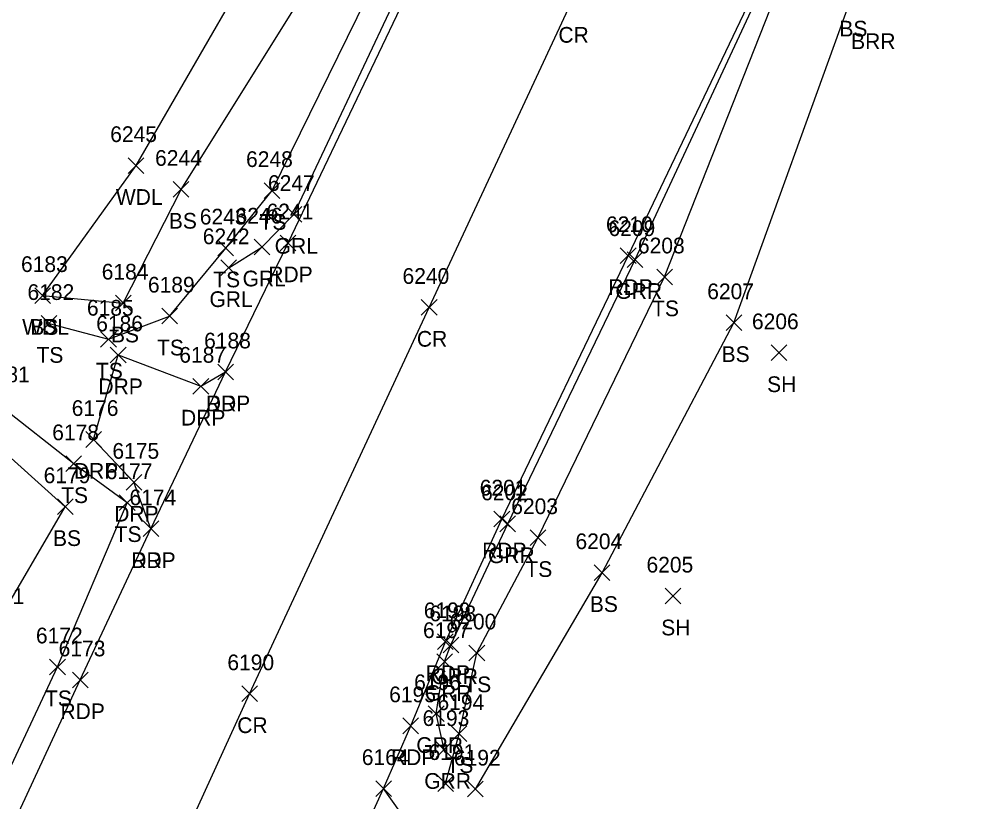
# Model space of a CAD drawing. Extents: x 1611797 to 1633212, y 298978 to 305475.
# Drawn here: x 1623086.6 to 1623208, y 302519.8 to 302619.4 of the extents above; entities that cross this region are included whole.
import ezdxf

# ---------------------------------------------------------------- set-up
doc = ezdxf.new("R2010")
doc.units = 0
for name, color, linetype in [('L_A', 7, 'Continuous'), ('L_I', 7, 'Continuous'), ('L_TIC', 7, 'Continuous'), ('LAWA', 7, 'Continuous'), ('LELB', 7, 'Continuous'), ('P_A', 7, 'Continuous'), ('P_I', 7, 'Continuous'), ('P_TIC', 7, 'Continuous'), ('PET', 7, 'Continuous'), ('PRC', 7, 'Continuous'), ('R_A', 7, 'Continuous'), ('R_I', 7, 'Continuous'), ('R_TIC', 7, 'Continuous'), ('RDP', 7, 'Continuous'), ('RGR', 7, 'Continuous')]:
    doc.layers.add(name, color=color, linetype=linetype)

msp = doc.modelspace()

# ---------------------------------------------------------------- linework, layer by layer
at = {"layer": 'L_TIC'}
for points in [[(1623100.54, 302599.79), (1623102.54, 302601.79)], [(1623102.54, 302599.79), (1623100.54, 302601.79)], [(1623106.26, 302596.76), (1623108.26, 302598.76)], [(1623108.26, 302596.76), (1623106.26, 302598.76)], [(1623117.84, 302596.61), (1623119.84, 302598.61)], [(1623119.84, 302596.61), (1623117.84, 302598.61)], [(1623111.95, 302589.29), (1623113.95, 302591.29)], [(1623113.95, 302589.29), (1623111.95, 302591.29)], [(1623167.79, 302585.61), (1623169.79, 302587.61)], [(1623169.79, 302585.61), (1623167.79, 302587.61)], [(1623088.63, 302583.24), (1623090.63, 302585.24)], [(1623090.63, 302583.24), (1623088.63, 302585.24)], [(1623088.63, 302583.24), (1623090.63, 302585.24)], [(1623090.63, 302583.24), (1623088.63, 302585.24)], [(1623098.9, 302582.28), (1623100.9, 302584.28)], [(1623100.9, 302582.28), (1623098.9, 302584.28)], [(1623104.79, 302580.62), (1623106.79, 302582.62)], [(1623106.79, 302580.62), (1623104.79, 302582.62)], [(1623089.45, 302579.68), (1623091.45, 302581.68)], [(1623091.45, 302579.68), (1623089.45, 302581.68)], [(1623176.61, 302579.78), (1623178.61, 302581.78)], [(1623178.61, 302579.78), (1623176.61, 302581.78)], [(1623097.02, 302577.68), (1623099.02, 302579.68)], [(1623099.02, 302577.68), (1623097.02, 302579.68)], [(1623182.35, 302575.95), (1623184.35, 302577.95)], [(1623184.35, 302575.95), (1623182.35, 302577.95)], [(1623092.6, 302561.82), (1623094.6, 302563.82)], [(1623094.6, 302561.82), (1623092.6, 302563.82)], [(1623091.52, 302556.35), (1623093.52, 302558.35)], [(1623093.52, 302556.35), (1623091.52, 302558.35)], [(1623099.4, 302556.86), (1623101.4, 302558.86)], [(1623101.4, 302556.86), (1623099.4, 302558.86)], [(1623151.67, 302552.41), (1623153.67, 302554.41)], [(1623153.67, 302552.41), (1623151.67, 302554.41)], [(1623159.84, 302547.95), (1623161.84, 302549.95)], [(1623161.84, 302547.95), (1623159.84, 302549.95)], [(1623168.87, 302544.97), (1623170.87, 302546.97)], [(1623170.87, 302544.97), (1623168.87, 302546.97)], [(1623143.9, 302537.73), (1623145.9, 302539.73)], [(1623145.9, 302537.73), (1623143.9, 302539.73)], [(1623090.53, 302535.95), (1623092.53, 302537.95)], [(1623092.53, 302535.95), (1623090.53, 302537.95)], [(1623141.63, 302527.45), (1623143.63, 302529.45)], [(1623143.63, 302527.45), (1623141.63, 302529.45)], [(1623139.92, 302521.1), (1623141.92, 302523.1)], [(1623141.92, 302521.1), (1623139.92, 302523.1)], [(1623143.72, 302520.39), (1623145.72, 302522.39)], [(1623145.72, 302520.39), (1623143.72, 302522.39)]]:
    msp.add_lwpolyline(points, dxfattribs=at)
at = {"layer": 'LAWA'}
msp.add_lwpolyline([(1623089.63, 302584.24), (1623101.54, 302600.79), (1623122.61, 302637.35), (1623140.17, 302675.92), (1623163.99, 302713.64)], dxfattribs=at)
at = {"layer": 'LELB'}
for points in [[(1623089.63, 302584.24), (1623099.9, 302583.28), (1623107.26, 302597.76), (1623129.85, 302633.91), (1623148.41, 302673.51), (1623161.31, 302708.12)], [(1623090.45, 302580.68), (1623098.02, 302578.68), (1623105.79, 302581.62), (1623112.95, 302590.29), (1623118.84, 302597.61), (1623135.63, 302631.86), (1623154.31, 302669.97), (1623172.76, 302707.09)], [(1623144.72, 302521.39), (1623160.84, 302548.95), (1623177.61, 302580.78), (1623192.6, 302622.23), (1623197.81, 302638.32), (1623201.61, 302657.13), (1623198.11, 302649.64), (1623197.81, 302649.3), (1623196.29, 302649.84)], [(1623140.92, 302522.1), (1623142.63, 302528.45), (1623144.9, 302538.73), (1623152.67, 302553.41), (1623168.79, 302586.61), (1623184.25, 302625.88), (1623194.89, 302644.22), (1623196.29, 302649.84), (1623195.84, 302653.9)], [(1622950.2, 302222.12), (1622969.04, 302263.04), (1622991.81, 302315.75), (1623013.56, 302366.12), (1623032.7, 302408.93), (1623054.15, 302459.64), (1623073.2, 302497.88), (1623091.53, 302536.95), (1623100.4, 302557.86), (1623093.6, 302562.82), (1623084.23, 302570.2)], [(1622931.41, 302188.46), (1622945.9, 302223.87), (1622965.15, 302265.23), (1622981.73, 302318.97), (1623007.17, 302368.65), (1623023.76, 302413.43), (1623043.88, 302464.02), (1623063.71, 302502.31), (1623083.53, 302541.97), (1623092.52, 302557.35), (1623082.99, 302565.85)]]:
    msp.add_lwpolyline(points, dxfattribs=at)
at = {"layer": 'P_TIC'}
for points in [[(1623119.88, 302589.94), (1623121.88, 302591.94)], [(1623121.88, 302589.94), (1623119.88, 302591.94)], [(1623163.16, 302588.32), (1623165.16, 302590.32)], [(1623165.16, 302588.32), (1623163.16, 302590.32)], [(1623137.83, 302581.73), (1623139.83, 302583.73)], [(1623139.83, 302581.73), (1623137.83, 302583.73)], [(1623111.93, 302573.51), (1623113.93, 302575.51)], [(1623113.93, 302573.51), (1623111.93, 302575.51)], [(1623147.08, 302554.78), (1623149.08, 302556.78)], [(1623149.08, 302554.78), (1623147.08, 302556.78)], [(1623102.43, 302553.54), (1623104.43, 302555.54)], [(1623104.43, 302553.54), (1623102.43, 302555.54)], [(1623139.9, 302539.16), (1623141.9, 302541.16)], [(1623141.9, 302539.16), (1623139.9, 302541.16)], [(1623093.42, 302534.3), (1623095.42, 302536.3)], [(1623095.42, 302534.3), (1623093.42, 302536.3)], [(1623114.97, 302532.53), (1623116.97, 302534.53)], [(1623116.97, 302532.53), (1623114.97, 302534.53)], [(1623135.48, 302528.45), (1623137.48, 302530.45)], [(1623137.48, 302528.45), (1623135.48, 302530.45)], [(1623132.04, 302520.46), (1623134.04, 302522.46)], [(1623134.04, 302520.46), (1623132.04, 302522.46)]]:
    msp.add_lwpolyline(points, dxfattribs=at)
at = {"layer": 'PET'}
for points in [[(1623120.03, 302492.78), (1623133.04, 302521.46), (1623136.48, 302529.45), (1623140.9, 302540.16), (1623148.08, 302555.78), (1623164.16, 302589.32), (1623182.09, 302626.91), (1623191.33, 302646.49), (1623194.97, 302654.45), (1623201.31, 302667.61), (1623213.02, 302692.54), (1623225.2, 302718.17), (1623242.57, 302754.17), (1623259.21, 302788.55), (1623275.23, 302819.9), (1623295.03, 302859.4), (1623316.4, 302901.79), (1623339.64, 302948.93), (1623359.43, 302990.05)], [(1623076.29, 302496.29), (1623094.42, 302535.3), (1623103.43, 302554.54), (1623112.93, 302574.51), (1623120.88, 302590.94), (1623139.35, 302629.62), (1623157.41, 302668.38), (1623174.94, 302705.43), (1623186.21, 302730.25), (1623197.28, 302753.3), (1623215.25, 302789.44), (1623239.94, 302839.72), (1623260.09, 302881.17), (1623281.2, 302923.51), (1623300.84, 302962.45)]]:
    msp.add_lwpolyline(points, dxfattribs=at)
at = {"layer": 'PRC'}
msp.add_lwpolyline([(1623094.71, 302486.97), (1623115.97, 302533.53), (1623138.83, 302582.73), (1623156.84, 302621.44), (1623174.33, 302658.65), (1623188.23, 302687.86), (1623204.65, 302721.63), (1623215.97, 302745.6), (1623233.17, 302781.9), (1623256.83, 302830.92), (1623277.73, 302872.44), (1623298.56, 302913.98), (1623318.04, 302953.14), (1623338.32, 302993.92), (1623366.3, 303050.96), (1623402.18, 303124.24), (1623426.64, 303170.43), (1623450.1, 303214.26), (1623478.76, 303269.12), (1623500.2, 303310.64), (1623518.37, 303345.45)], dxfattribs=at)
at = {"layer": 'R_TIC'}
for points in [[(1623120.62, 302593.57), (1623122.62, 302595.57)], [(1623122.62, 302593.57), (1623120.62, 302595.57)], [(1623116.55, 302589.41), (1623118.55, 302591.41)], [(1623118.55, 302589.41), (1623116.55, 302591.41)], [(1623164.04, 302587.82), (1623166.04, 302589.82)], [(1623166.04, 302587.82), (1623164.04, 302589.82)], [(1623112.32, 302586.78), (1623114.32, 302588.78)], [(1623114.32, 302586.78), (1623112.32, 302588.78)], [(1623098.25, 302575.68), (1623100.25, 302577.68)], [(1623100.25, 302575.68), (1623098.25, 302577.68)], [(1623111.93, 302573.51), (1623113.93, 302575.51)], [(1623113.93, 302573.51), (1623111.93, 302575.51)], [(1623108.77, 302571.69), (1623110.77, 302573.69)], [(1623110.77, 302571.69), (1623108.77, 302573.69)], [(1623095.13, 302564.91), (1623097.13, 302566.91)], [(1623097.13, 302564.91), (1623095.13, 302566.91)], [(1623100.26, 302559.46), (1623102.26, 302561.46)], [(1623102.26, 302559.46), (1623100.26, 302561.46)], [(1623147.83, 302554.17), (1623149.83, 302556.17)], [(1623149.83, 302554.17), (1623147.83, 302556.17)], [(1623102.43, 302553.54), (1623104.43, 302555.54)], [(1623104.43, 302553.54), (1623102.43, 302555.54)], [(1623140.6, 302538.76), (1623142.6, 302540.76)], [(1623142.6, 302538.76), (1623140.6, 302540.76)], [(1623139.79, 302536.63), (1623141.79, 302538.63)], [(1623141.79, 302536.63), (1623139.79, 302538.63)], [(1623138.72, 302530), (1623140.72, 302532)], [(1623140.72, 302530), (1623138.72, 302532)], [(1623139.73, 302525.43), (1623141.73, 302527.43)], [(1623141.73, 302525.43), (1623139.73, 302527.43)], [(1623132.04, 302520.46), (1623134.04, 302522.46)], [(1623134.04, 302520.46), (1623132.04, 302522.46)]]:
    msp.add_lwpolyline(points, dxfattribs=at)
at = {"layer": 'RDP'}
for points in [[(1623103.43, 302554.54), (1623101.26, 302560.46), (1623096.13, 302565.91), (1623099.25, 302576.68), (1623109.77, 302572.69), (1623112.93, 302574.51)], [(1623145.1, 302499.57), (1623139.45, 302512.37), (1623133.04, 302521.46)]]:
    msp.add_lwpolyline(points, dxfattribs=at)
at = {"layer": 'RGR'}
for points in [[(1623113.32, 302587.78), (1623117.55, 302590.41), (1623121.62, 302594.57), (1623138.73, 302630.93), (1623156.64, 302668.69), (1623174.15, 302705.56)], [(1623140.73, 302526.43), (1623139.72, 302531), (1623140.79, 302537.63), (1623141.6, 302539.76), (1623148.83, 302555.17), (1623165.04, 302588.82), (1623182.74, 302626.84), (1623192.05, 302645.51), (1623195.84, 302653.9), (1623201.51, 302667.04)]]:
    msp.add_lwpolyline(points, dxfattribs=at)

# ---------------------------------------------------------------- texts
at = {"layer": 'L_A'}
for s, p in [('BS', (1623191.04, 302617.23)), ('BRR', (1623192.53, 302615.63)), ('WDL', (1623098.96, 302595.79)), ('BS', (1623105.7, 302592.76)), ('TS', (1623117.25, 302592.61)), ('TS', (1623111.36, 302585.29)), ('TS', (1623167.2, 302581.61)), ('WDL', (1623087.04, 302579.24)), ('BS', (1623088.07, 302579.24)), ('BS', (1623098.34, 302578.28)), ('TS', (1623088.86, 302575.68)), ('TS', (1623104.2, 302576.62)), ('BS', (1623176.05, 302575.78)), ('TS', (1623096.43, 302573.68)), ('SH', (1623181.84, 302571.95)), ('TS', (1623092, 302557.82)), ('TS', (1623098.81, 302552.86)), ('BS', (1623090.96, 302552.35)), ('TS', (1623151.08, 302548.41)), ('BS', (1623159.28, 302543.95)), ('SH', (1623168.36, 302540.97)), ('TS', (1623143.31, 302533.73)), ('TS', (1623089.94, 302531.95)), ('TS', (1623141.04, 302523.45))]:
    msp.add_text(s, height=2, dxfattribs=at).set_placement(p)
at = {"layer": 'L_I'}
for s, p in [('6245', (1623098.24, 302603.79)), ('6244', (1623103.95, 302600.76)), ('6248', (1623115.53, 302600.61)), ('6243', (1623109.64, 302593.29)), ('6208', (1623165.4, 302589.61)), ('6183', (1623086.89, 302587.24)), ('6183', (1623086.89, 302587.24)), ('6184', (1623097.16, 302586.28)), ('6189', (1623103.04, 302584.62)), ('6182', (1623087.71, 302583.68)), ('6207', (1623174.22, 302583.78)), ('6185', (1623095.28, 302581.68)), ('6206', (1623179.91, 302579.95)), ('6181', (1623082.05, 302573.2)), ('6178', (1623090.86, 302565.82)), ('6179', (1623089.77, 302560.35)), ('6177', (1623097.66, 302560.86)), ('6203', (1623149.28, 302556.41)), ('6204', (1623157.45, 302551.95)), ('6205', (1623166.49, 302548.97)), ('6171', (1623081.35, 302544.97)), ('6200', (1623141.43, 302541.73)), ('6172', (1623088.79, 302539.95)), ('6194', (1623139.89, 302531.45)), ('6191', (1623138.75, 302525.1)), ('6192', (1623141.98, 302524.39))]:
    msp.add_text(s, height=2, dxfattribs=at).set_placement(p)
at = {"layer": 'P_A'}
for s, p in [('CR', (1623155.28, 302616.44)), ('RDP', (1623118.36, 302585.94)), ('RDP', (1623161.64, 302584.32)), ('CR', (1623137.27, 302577.73)), ('RDP', (1623110.41, 302569.51)), ('RDP', (1623145.57, 302550.78)), ('RDP', (1623100.92, 302549.54)), ('RDP', (1623138.39, 302535.16)), ('RDP', (1623091.91, 302530.3)), ('CR', (1623114.41, 302528.53)), ('RDP', (1623133.97, 302524.45))]:
    msp.add_text(s, height=2, dxfattribs=at).set_placement(p)
at = {"layer": 'P_I'}
for s, p in [('6241', (1623118.14, 302593.94)), ('6210', (1623161.33, 302592.32)), ('6240', (1623135.44, 302585.73)), ('6188', (1623110.19, 302577.51)), ('6201', (1623145.26, 302558.78)), ('6174', (1623100.69, 302557.54)), ('6199', (1623138.15, 302543.16)), ('6173', (1623091.68, 302538.3)), ('6190', (1623113.15, 302536.53)), ('6195', (1623133.74, 302532.45)), ('6164', (1623130.26, 302524.46))]:
    msp.add_text(s, height=2, dxfattribs=at).set_placement(p)
at = {"layer": 'R_A'}
for s, p in [('GRL', (1623119.17, 302589.57)), ('GRL', (1623115.09, 302585.41)), ('GRR', (1623162.53, 302583.82)), ('GRL', (1623110.87, 302582.78)), ('DRP', (1623096.74, 302571.68)), ('DRP', (1623110.41, 302569.51)), ('DRP', (1623107.25, 302567.69)), ('DRP', (1623093.62, 302560.91)), ('DRP', (1623098.75, 302555.46)), ('GRR', (1623146.32, 302550.17)), ('DRP', (1623100.92, 302549.54)), ('GRR', (1623139.09, 302534.76)), ('GRR', (1623138.28, 302532.63)), ('GRR', (1623137.2, 302526)), ('GRR', (1623138.21, 302521.43))]:
    msp.add_text(s, height=2, dxfattribs=at).set_placement(p)
at = {"layer": 'R_I'}
for s, p in [('6247', (1623118.32, 302597.57)), ('6246', (1623114.19, 302593.41)), ('6209', (1623161.65, 302591.82)), ('6242', (1623110.02, 302590.78)), ('6186', (1623096.46, 302579.68)), ('6188', (1623110.19, 302577.51)), ('6187', (1623107.03, 302575.69)), ('6176', (1623093.34, 302568.91)), ('6175', (1623098.52, 302563.46)), ('6174', (1623100.69, 302557.54)), ('6202', (1623145.44, 302558.17)), ('6198', (1623138.86, 302542.76)), ('6197', (1623138.05, 302540.63)), ('6196', (1623136.92, 302534)), ('6193', (1623137.99, 302529.43)), ('6164', (1623130.26, 302524.46))]:
    msp.add_text(s, height=2, dxfattribs=at).set_placement(p)

doc.saveas('drawing.dxf')
